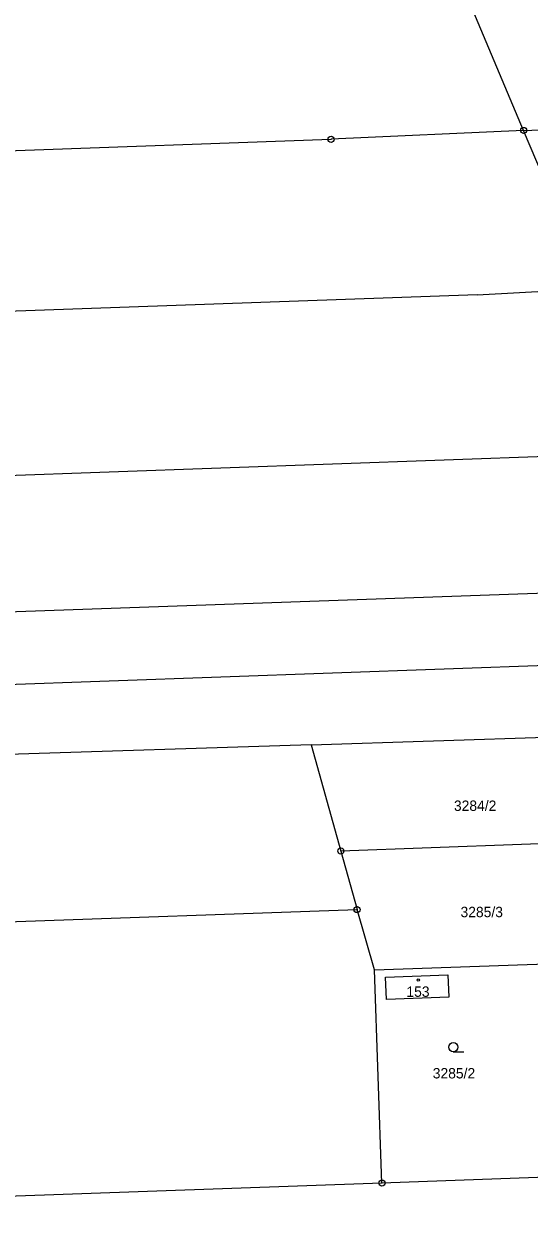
# Model space of a CAD drawing. Extents: x -618848 to -615803, y -1044450 to -1042254.
# Drawn here: x -617311.9 to -617229.1, y -1043340.2 to -1043145.8 of the extents above; entities that cross this region are included whole.
import ezdxf
from ezdxf.enums import TextEntityAlignment as Align

# ---------------------------------------------------------------- set-up
doc = ezdxf.new("R2010")
doc.units = 0
doc.header["$LTSCALE"] = 0.68
for name, color, linetype, lineweight in [('1', 7, 'Continuous', 25), ('3', 7, 'Continuous', 25), ('5', 7, 'Continuous', 25), ('8', 7, 'Continuous', 25)]:
    doc.layers.add(name, color=color, linetype=linetype, lineweight=lineweight)
doc.layers.add('2', color=7, linetype='Continuous')

msp = doc.modelspace()

# ---------------------------------------------------------------- linework, layer by layer
at = {"layer": '1'}
for p, q in [((-617230, -1043163.35), (-617239.33, -1043141.18)), ((-617230, -1043163.35), (-617261.54, -1043164.8)), ((-617230, -1043163.35), (-617225.95, -1043163.17)), ((-617219.09, -1043189.28), (-617230, -1043163.35)), ((-617412.15, -1043170.15), (-617261.54, -1043164.8)), ((-617237.59, -1043190.31), (-617222.1, -1043189.45)), ((-617237.59, -1043190.31), (-617427.92, -1043197.08)), ((-617328.52, -1043220.4), (-617213.45, -1043216.31)), ((-617216.36, -1043238.84), (-617335.78, -1043243.08)), ((-617338.34, -1043255.02), (-617215.66, -1043250.66)), ((-617264.81, -1043264.08), (-617215.38, -1043262.49)), ((-617264.81, -1043264.08), (-617342.05, -1043266.56)), ((-617353.14, -1043294.5), (-617257.28, -1043291.09)), ((-617254.45, -1043300.97), (-617257.28, -1043291.09)), ((-617254.45, -1043300.97), (-617215.69, -1043299.59)), ((-617253.21, -1043335.94), (-617254.45, -1043300.97)), ((-617252.62, -1043302.16), (-617242.41, -1043301.77)), ((-617252.47, -1043305.83), (-617252.62, -1043302.16)), ((-617242.41, -1043301.77), (-617242.28, -1043305.44)), ((-617242.28, -1043305.44), (-617252.47, -1043305.83)), ((-617213.24, -1043334.52), (-617253.21, -1043335.94)), ((-617253.21, -1043335.94), (-617374.38, -1043340.24))]:
    msp.add_line(p, q, dxfattribs=at)
for points in [[(-617264.81, -1043264.08), (-617259.95, -1043281.5), (-617257.28, -1043291.09)], [(-617215.62, -1043287.72), (-617215.55, -1043279.86), (-617259.95, -1043281.5)]]:
    msp.add_lwpolyline(points, dxfattribs=at)
at = {"layer": '3'}
msp.add_line((-617241.523, -1043314.41), (-617239.773, -1043314.41), dxfattribs=at)
msp.add_circle((-617241.5229, -1043313.6598), 0.75, dxfattribs=at)
at = {"layer": '5'}
msp.add_circle((-617247.2568, -1043302.6492), 0.175, dxfattribs=at)
at = {"layer": '8'}
for centre, radius in [((-617261.54, -1043164.7999), 0.5), ((-617230, -1043163.3499), 0.5), ((-617230, -1043163.3499), 0.0303), ((-617261.54, -1043164.7999), 0.0303), ((-617259.95, -1043281.4999), 0.5), ((-617259.95, -1043281.4999), 0.0303), ((-617257.28, -1043291.0899), 0.5), ((-617257.28, -1043291.0899), 0.0303), ((-617253.21, -1043335.9399), 0.5), ((-617253.21, -1043335.9399), 0.0303)]:
    msp.add_circle(centre, radius, dxfattribs=at)

# ---------------------------------------------------------------- texts
at = {"layer": '2'}
for s, p in [('3284/2', (-617237.94, -1043274.915)), ('3285/3', (-617236.86, -1043292.345)), ('153', (-617247.309, -1043305.405)), ('3285/2', (-617241.41, -1043318.785))]:
    msp.add_text(s, height=1.7, dxfattribs=at).set_placement(p, align=Align.CENTER)

doc.saveas('drawing.dxf')
